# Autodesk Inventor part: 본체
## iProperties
Created: 2015-03
Part Number: 본체
Document SubType Name: Modeling
Designer: 102-022
Density: 2.71 g/cm^3
Material: 알루미늄-6061
Mass: 466.254 g
Surface Area: 342.901 cm^2
Volume: 172.049 cm^3
Author: 102-022
